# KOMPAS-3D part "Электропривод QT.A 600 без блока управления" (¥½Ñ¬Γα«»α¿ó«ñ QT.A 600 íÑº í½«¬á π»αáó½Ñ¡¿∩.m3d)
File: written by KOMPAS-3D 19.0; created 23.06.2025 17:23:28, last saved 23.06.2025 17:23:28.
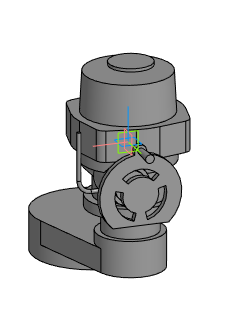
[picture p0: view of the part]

Document properties: Автор: Евгений; Полное имя файла: E:\Dendor Работа Сачек\3D для проектировщиков\3.5 Тип QT.А Электропривод\stp_Электропривод QT.A без блока управления\Электропривод QT.A 600 без блока управления.m3d

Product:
- Part/product: Электропривод QT.A 600 без блока управления

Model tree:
1. Операция без истории:1  (labels: Электропривод QT.A 600 без блока управления)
